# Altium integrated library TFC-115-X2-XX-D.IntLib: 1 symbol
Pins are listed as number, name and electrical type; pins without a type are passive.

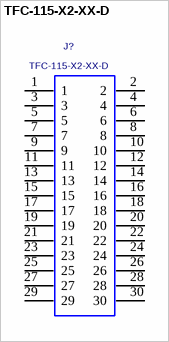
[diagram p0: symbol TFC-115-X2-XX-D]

## TFC-115-X2-XX-D
designator J?
0.050" TERMINAL STRIP, SURFACE MOUNT ASSEMBLY.; MANUFACTURER: SAMTEC
footprint TFC-115-X2-XX-D
pins: 1, 2, 3, 4, 5, 6, 7, 8, 9, 10, 11, 12, 13, 14, 15, 16, 17, 18, 19, 20, 21, 22, 23, 24, 25, 26, 27, 28, 29, 30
